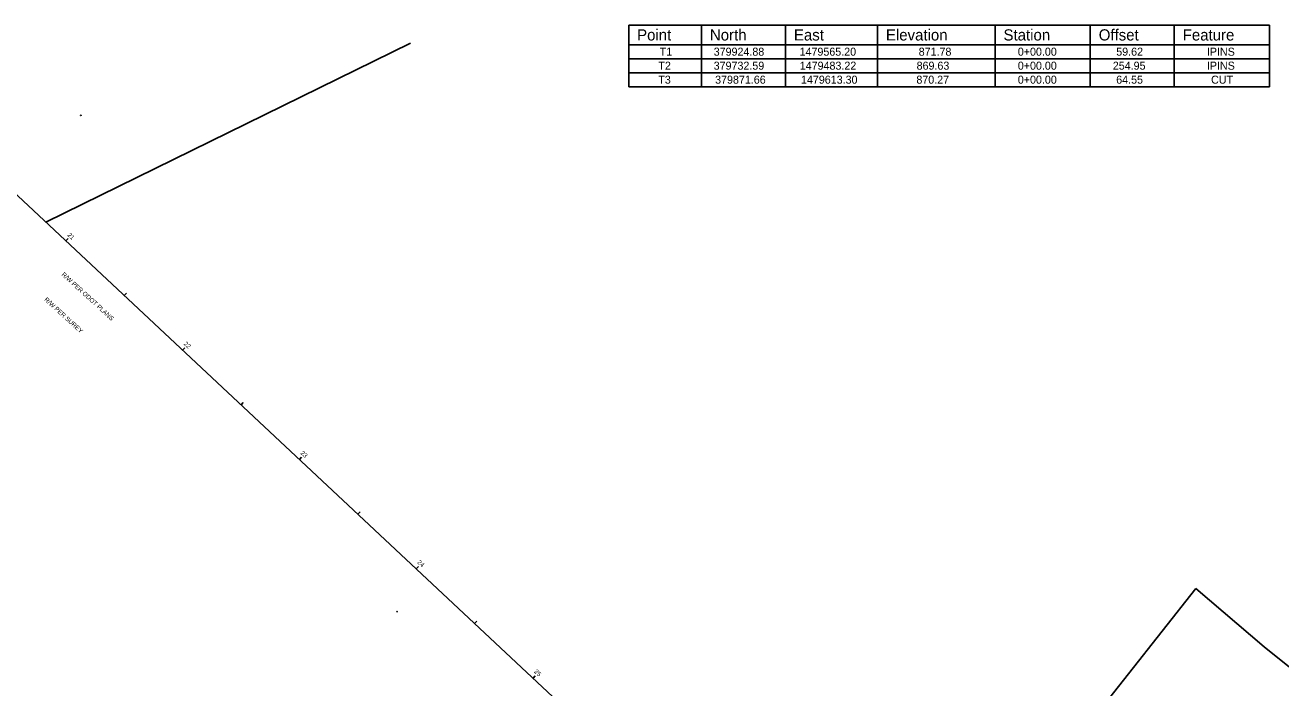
# Model space of a CAD drawing. Extents: x 1474076 to 1484331, y 375914 to 383395.
# Drawn here: x 1479629 to 1480414, y 379628 to 380042 of the extents above; entities that cross this region are included whole.
import ezdxf

# ---------------------------------------------------------------- set-up
doc = ezdxf.new("R2010")
doc.units = 0
for name, color, linetype in [('Default', 7, 'Continuous'), ('DV_X_Lot_Line', 7, 'Continuous'), ('RW_P_Esmt_TMP', 7, 'Continuous'), ('SV_Control_Point', 7, 'Continuous'), ('SV_P_Control_Cells_Set', 7, 'Continuous'), ('SV_P_Mon_Cells_Set', 7, 'Continuous')]:
    doc.layers.add(name, color=color, linetype=linetype)

msp = doc.modelspace()

# ---------------------------------------------------------------- linework, layer by layer
at = {"layer": 'Default'}
for p, q in [((1480006.61, 380041.98), (1480407.11, 380041.98)), ((1480006.61, 380041.98), (1480006.61, 380003.48)), ((1480052.11, 380041.98), (1480052.11, 380003.48)), ((1480104.61, 380041.98), (1480104.61, 380003.48)), ((1480162.11, 380041.98), (1480162.11, 380003.48)), ((1480235.61, 380041.98), (1480235.61, 380003.48)), ((1480295.11, 380041.98), (1480295.11, 380003.48)), ((1480347.61, 380041.98), (1480347.61, 380003.48)), ((1480407.11, 380041.98), (1480407.11, 380003.48)), ((1480407.11, 380041.98), (1480407.11, 380003.48)), ((1480006.61, 380029.73), (1480407.11, 380029.73)), ((1480006.61, 380020.98), (1480407.11, 380020.98)), ((1480006.61, 380020.98), (1480407.11, 380020.98)), ((1480006.61, 380020.98), (1480407.11, 380020.98)), ((1480006.61, 380020.98), (1480407.11, 380020.98)), ((1480006.61, 380020.98), (1480407.11, 380020.98)), ((1480006.61, 380020.98), (1480407.11, 380020.98)), ((1480006.61, 380020.98), (1480407.11, 380020.98)), ((1480006.61, 380012.23), (1480407.11, 380012.23)), ((1480006.61, 380012.23), (1480407.11, 380012.23)), ((1480006.61, 380012.23), (1480407.11, 380012.23)), ((1480006.61, 380012.23), (1480407.11, 380012.23)), ((1480006.61, 380012.23), (1480407.11, 380012.23)), ((1480006.61, 380012.23), (1480407.11, 380012.23)), ((1480006.61, 380012.23), (1480407.11, 380012.23)), ((1480006.61, 380003.48), (1480407.11, 380003.48)), ((1480006.61, 380003.48), (1480407.11, 380003.48)), ((1480006.61, 380003.48), (1480407.11, 380003.48)), ((1480006.61, 380003.48), (1480407.11, 380003.48)), ((1480006.61, 380003.48), (1480407.11, 380003.48)), ((1480006.61, 380003.48), (1480407.11, 380003.48)), ((1480006.61, 380003.48), (1480407.11, 380003.48))]:
    msp.add_line(p, q, dxfattribs=at)
at = {"layer": 'DV_X_Lot_Line'}
for p, q in [((1480261.85, 379563.88), (1480361.09, 379689.7)), ((1480361.09, 379689.7), (1480403.85, 379653.14)), ((1480403.85, 379653.14), (1480549.78, 379536.04))]:
    msp.add_line(p, q, dxfattribs=at)
at = {"layer": 'RW_P_Esmt_TMP'}
for p, q in [((1479642.33, 379918.73), (1479870.13, 380030.67)), ((1479566.7, 379989.54), (1480555.97, 379063.33)), ((1479654.81, 379907.04), (1479656.18, 379908.5)), ((1479691.31, 379872.87), (1479692.68, 379874.33)), ((1479727.81, 379838.69), (1479729.18, 379840.15)), ((1479764.31, 379804.52), (1479765.68, 379805.98)), ((1479800.81, 379770.35), (1479802.18, 379771.81)), ((1479837.31, 379736.18), (1479838.68, 379737.64)), ((1479873.81, 379702), (1479875.18, 379703.46)), ((1479910.31, 379667.83), (1479911.68, 379669.29)), ((1479946.81, 379633.66), (1479948.18, 379635.12))]:
    msp.add_line(p, q, dxfattribs=at)
at = {"layer": 'SV_P_Control_Cells_Set'}
for points in [[(1479861.9, 379675.19), (1479861.9, 379675.27), (1479861.93, 379675.27), (1479861.93, 379675.27), (1479861.93, 379675.26), (1479861.93, 379675.26), (1479861.94, 379675.26), (1479861.94, 379675.26), (1479861.94, 379675.26), (1479861.94, 379675.25), (1479861.94, 379675.24), (1479861.94, 379675.24), (1479861.94, 379675.24), (1479861.94, 379675.23), (1479861.93, 379675.23), (1479861.93, 379675.23), (1479861.93, 379675.23), (1479861.93, 379675.23), (1479861.9, 379675.23)], [(1479861.98, 379675.2), (1479861.98, 379675.2), (1479861.99, 379675.2), (1479861.99, 379675.19), (1479861.99, 379675.19), (1479861.99, 379675.19), (1479861.98, 379675.19), (1479861.98, 379675.19), (1479861.98, 379675.19), (1479861.98, 379675.19), (1479861.98, 379675.19), (1479861.98, 379675.2), (1479861.98, 379675.2)], [(1479862.05, 379675.27), (1479862.01, 379675.27), (1479862.01, 379675.19)], [(1479862.01, 379675.23), (1479862.04, 379675.23)], [(1479862.09, 379675.2), (1479862.09, 379675.2), (1479862.09, 379675.2), (1479862.09, 379675.19), (1479862.09, 379675.19), (1479862.09, 379675.19), (1479862.09, 379675.19), (1479862.09, 379675.19), (1479862.09, 379675.19), (1479862.09, 379675.19), (1479862.09, 379675.19), (1479862.09, 379675.2), (1479862.09, 379675.2)]]:
    msp.add_lwpolyline(points, dxfattribs=at)
for radius in [0.06, 0.0247]:
    msp.add_circle((1479861.8, 379675.23), radius, dxfattribs=at)
at = {"layer": 'SV_P_Mon_Cells_Set'}
for points in [[(1479664.15, 379985.57), (1479664.17, 379985.57)], [(1479664.15, 379985.49), (1479664.17, 379985.49)], [(1479664.16, 379985.49), (1479664.16, 379985.57)], [(1479664.21, 379985.5), (1479664.21, 379985.5), (1479664.22, 379985.5), (1479664.22, 379985.5), (1479664.22, 379985.49), (1479664.22, 379985.49), (1479664.21, 379985.49), (1479664.21, 379985.49), (1479664.21, 379985.49), (1479664.21, 379985.49), (1479664.21, 379985.5), (1479664.21, 379985.5), (1479664.21, 379985.5)], [(1479664.24, 379985.49), (1479664.24, 379985.57), (1479664.27, 379985.57), (1479664.27, 379985.57), (1479664.27, 379985.57), (1479664.28, 379985.57), (1479664.28, 379985.56), (1479664.28, 379985.56), (1479664.28, 379985.56), (1479664.28, 379985.55), (1479664.28, 379985.55), (1479664.28, 379985.54), (1479664.28, 379985.54), (1479664.28, 379985.54), (1479664.28, 379985.53), (1479664.27, 379985.53), (1479664.27, 379985.53), (1479664.27, 379985.53), (1479664.24, 379985.53)], [(1479664.32, 379985.5), (1479664.33, 379985.5), (1479664.33, 379985.5), (1479664.33, 379985.5), (1479664.33, 379985.49), (1479664.33, 379985.49), (1479664.33, 379985.49), (1479664.32, 379985.49), (1479664.32, 379985.49), (1479664.32, 379985.49), (1479664.32, 379985.5), (1479664.32, 379985.5), (1479664.32, 379985.5)], [(1479664.39, 379985.56), (1479664.39, 379985.56), (1479664.39, 379985.57), (1479664.38, 379985.57), (1479664.38, 379985.57), (1479664.37, 379985.57), (1479664.37, 379985.57), (1479664.36, 379985.57), (1479664.36, 379985.56), (1479664.35, 379985.56), (1479664.35, 379985.55), (1479664.35, 379985.55), (1479664.35, 379985.54), (1479664.36, 379985.54), (1479664.39, 379985.52), (1479664.39, 379985.52), (1479664.39, 379985.52), (1479664.39, 379985.51), (1479664.39, 379985.51), (1479664.39, 379985.51), (1479664.39, 379985.5), (1479664.39, 379985.5), (1479664.39, 379985.5), (1479664.39, 379985.49), (1479664.39, 379985.49), (1479664.39, 379985.49), (1479664.38, 379985.49), (1479664.38, 379985.49), (1479664.38, 379985.49), (1479664.37, 379985.49), (1479664.37, 379985.49), (1479664.36, 379985.49), (1479664.35, 379985.5)], [(1479664.43, 379985.5), (1479664.44, 379985.5), (1479664.44, 379985.5), (1479664.44, 379985.5), (1479664.44, 379985.49), (1479664.44, 379985.49), (1479664.44, 379985.49), (1479664.43, 379985.49), (1479664.43, 379985.49), (1479664.43, 379985.49), (1479664.43, 379985.5), (1479664.43, 379985.5), (1479664.43, 379985.5)]]:
    msp.add_lwpolyline(points, dxfattribs=at)
msp.add_circle((1479664.05, 379985.53), 0.06, dxfattribs=at)

# ---------------------------------------------------------------- texts
at = {"layer": 'Default'}
for s, height, p in [('Point', 7, (1480011.86, 380032.36)), ('North', 7, (1480057.36, 380032.36)), ('East', 7, (1480109.86, 380032.36)), ('Elevation', 7, (1480167.36, 380032.36)), ('Station', 7, (1480240.86, 380032.36)), ('Offset', 7, (1480300.36, 380032.36)), ('Feature', 7, (1480352.86, 380032.36)), ('T1', 5, (1480025.98, 380022.86)), ('379924.88', 5, (1480059.72, 380022.86)), ('1479565.20', 5, (1480113.4, 380022.86)), ('871.78', 5, (1480187.84, 380022.86)), ('0+00.00', 5, (1480249.79, 380022.86)), ('59.62', 5, (1480311.3, 380022.86)), ('IPINS', 5, (1480367.95, 380022.86)), ('T2', 5, (1480025.15, 380014.11)), ('379732.59', 5, (1480059.7, 380014.11)), ('1479483.22', 5, (1480113.5, 380014.11)), ('869.63', 5, (1480186.54, 380014.11)), ('0+00.00', 5, (1480249.79, 380014.11)), ('254.95', 5, (1480309.16, 380014.11)), ('IPINS', 5, (1480367.95, 380014.11)), ('T3', 5, (1480025.09, 380005.36)), ('379871.66', 5, (1480060.61, 380005.36)), ('1479613.30', 5, (1480114.27, 380005.36)), ('870.27', 5, (1480186.4, 380005.36)), ('0+00.00', 5, (1480249.79, 380005.36)), ('64.55', 5, (1480311.28, 380005.36)), ('CUT', 5, (1480370.59, 380005.36))]:
    msp.add_text(s, height=height, dxfattribs=at).set_placement(p)
at = {"layer": 'RW_P_Esmt_TMP'}
for s, p in [('21', (1479655.57, 379910.44)), ('22', (1479728.23, 379842.41)), ('23', (1479801.21, 379774.09)), ('24', (1479874.24, 379705.71)), ('25', (1479947.21, 379637.39))]:
    msp.add_text(s, height=2.8, rotation=316.88585, dxfattribs=at).set_placement(p)
at = {"layer": 'SV_Control_Point'}
for s, p in [('R/W PER ODOT PLANS', (1479651.85, 379885.66)), ('R/W PER SUREY', (1479641.08, 379869.97))]:
    msp.add_text(s, height=2.8, rotation=317.53306, dxfattribs=at).set_placement(p)

doc.saveas('drawing.dxf')
